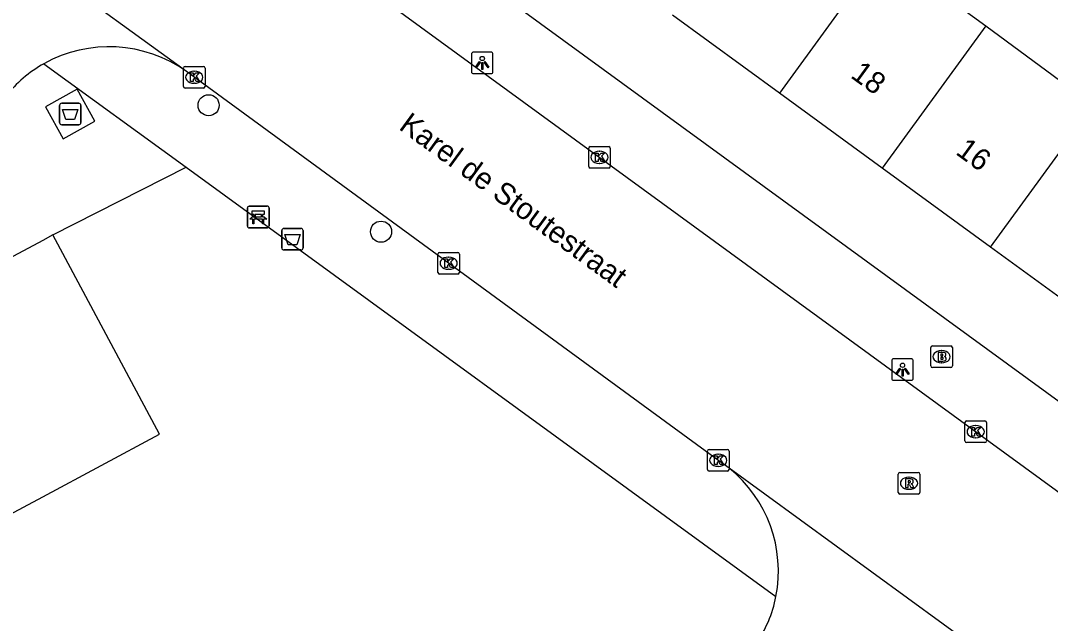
# Model space of a CAD drawing. Extents: x 159675 to 160530, y 382179 to 382901.
# Drawn here: x 159998.97 to 160046.7, y 382350.18 to 382378.09 of the extents above; entities that cross this region are included whole.
import ezdxf

# ---------------------------------------------------------------- set-up
doc = ezdxf.new("R2010")
doc.units = 0
for name, color, linetype in [('IMGEO_Afval_apart_plaats', 7, 'Continuous'), ('IMGEO_Afvalbak', 7, 'Continuous'), ('IMGEO_Bank', 7, 'Continuous'), ('IMGEO_Boom', 7, 'Continuous'), ('IMGEO_Brandkraan', 7, 'Continuous'), ('IMGEO_Kolk', 7, 'Continuous'), ('IMGEO_Lichtpunt', 7, 'Continuous'), ('IMGEO_Openbare_ruimte_label', 7, 'Continuous'), ('IMGEO_Pand', 7, 'Continuous'), ('IMGEO_Pand_nummerreeks', 7, 'Continuous'), ('IMGEO_Rijbaan_lokaal_gesloten', 7, 'Continuous'), ('IMGEO_Rijbaan_lokaal_open', 7, 'Continuous'), ('IMGEO_Rioolput', 7, 'Continuous'), ('IMGEO_Voetpad_gesloten', 7, 'Continuous'), ('IMGEO_Voetpad_open', 7, 'Continuous')]:
    doc.layers.add(name, color=color, linetype=linetype)

msp = doc.modelspace()

# ---------------------------------------------------------------- linework, layer by layer
at = {"layer": 'IMGEO_Afval_apart_plaats'}
for p, q in [((160000.777, 382373.368), (160000.777, 382374.168)), ((160000.777, 382374.168), (160000.777, 382373.368)), ((160000.877, 382374.268), (160001.667, 382374.268)), ((160001.667, 382374.268), (160000.877, 382374.268)), ((160001.767, 382374.168), (160001.767, 382373.368)), ((160001.767, 382373.368), (160001.767, 382374.168)), ((160001.667, 382373.268), (160000.877, 382373.268)), ((160000.877, 382373.268), (160001.667, 382373.268))]:
    msp.add_line(p, q, dxfattribs=at)
msp.add_lwpolyline([(160000.92, 382373.982), (160001.624, 382373.982), (160001.475, 382373.512), (160001.069, 382373.512), (160000.92, 382373.982)], dxfattribs=at)
for centre, start, end in [((160000.877, 382374.168), 90, 180), ((160000.877, 382374.168), 90, 180), ((160001.667, 382374.168), 0, 90), ((160001.667, 382374.168), 360, 90), ((160000.877, 382373.368), 180, 270), ((160000.877, 382373.368), 180, 270), ((160001.667, 382373.368), 270, 0), ((160001.667, 382373.368), 270, 0)]:
    msp.add_arc(centre, 0.1, start, end, dxfattribs=at)
at = {"layer": 'IMGEO_Afvalbak'}
for p, q in [((160011.077, 382367.57), (160011.077, 382368.37)), ((160011.077, 382368.37), (160011.077, 382367.57)), ((160011.177, 382368.47), (160011.967, 382368.47)), ((160011.967, 382368.47), (160011.177, 382368.47)), ((160012.067, 382368.37), (160012.067, 382367.57)), ((160012.067, 382367.57), (160012.067, 382368.37)), ((160011.967, 382367.47), (160011.177, 382367.47)), ((160011.177, 382367.47), (160011.967, 382367.47))]:
    msp.add_line(p, q, dxfattribs=at)
msp.add_lwpolyline([(160011.22, 382368.184), (160011.924, 382368.184), (160011.775, 382367.714), (160011.369, 382367.714), (160011.22, 382368.184)], dxfattribs=at)
for centre, start, end in [((160011.177, 382368.37), 90, 180), ((160011.177, 382368.37), 90, 180), ((160011.967, 382368.37), 0, 90), ((160011.967, 382368.37), 360, 90), ((160011.177, 382367.57), 180, 270), ((160011.177, 382367.57), 180, 270), ((160011.967, 382367.57), 270, 0), ((160011.967, 382367.57), 270, 0)]:
    msp.add_arc(centre, 0.1, start, end, dxfattribs=at)
at = {"layer": 'IMGEO_Bank'}
for p, q in [((160009.486, 382368.574), (160009.486, 382369.415)), ((160009.486, 382369.415), (160009.486, 382368.574)), ((160009.561, 382369.499), (160010.402, 382369.499)), ((160010.402, 382369.499), (160009.561, 382369.499)), ((160010.486, 382369.424), (160010.486, 382368.583)), ((160010.486, 382368.583), (160010.486, 382369.424)), ((160010.183, 382368.897), (160009.79, 382368.897)), ((160009.795, 382369.005), (160009.795, 382369.111)), ((160009.839, 382369.111), (160009.839, 382369.005)), ((160010.127, 382369.117), (160009.845, 382369.117)), ((160009.845, 382368.999), (160010.127, 382368.999)), ((160010.133, 382369.005), (160010.133, 382369.111)), ((160010.177, 382369.111), (160010.177, 382369.005)), ((160010.411, 382368.499), (160009.57, 382368.499)), ((160009.57, 382368.499), (160010.411, 382368.499))]:
    msp.add_line(p, q, dxfattribs=at)
for points in [[(160009.789, 382369.117), (160009.703, 382369.117), (160009.703, 382369.278), (160010.266, 382369.278), (160010.266, 382369.117), (160010.183, 382369.117)], [(160009.733, 382368.897), (160009.591, 382368.897), (160009.703, 382368.999), (160009.789, 382368.999)], [(160009.783, 382368.89), (160009.783, 382368.683), (160009.74, 382368.683), (160009.74, 382368.89)], [(160010.183, 382368.999), (160010.266, 382368.999), (160010.378, 382368.897), (160010.239, 382368.897)], [(160010.233, 382368.89), (160010.233, 382368.683), (160010.189, 382368.683), (160010.189, 382368.89)]]:
    msp.add_lwpolyline(points, dxfattribs=at)
for centre, radius, start, end in [((160009.564, 382369.421), 0.0779, 92.4484, 184.2845), ((160009.564, 382369.421), 0.0779, 92.4484, 184.2845), ((160010.408, 382369.421), 0.0779, 2.4484, 94.2845), ((160010.408, 382369.421), 0.0779, 2.4484, 94.2845), ((160009.733, 382368.89), 0.00671, 2.8957, 87.1043), ((160009.79, 382368.89), 0.00671, 92.8957, 177.1043), ((160009.788, 382369.11), 0.00671, 2.8957, 87.1043), ((160009.788, 382369.006), 0.00671, 272.8957, 357.1043), ((160009.845, 382369.11), 0.00671, 92.8957, 177.1043), ((160009.845, 382369.006), 0.00671, 182.8957, 267.1043), ((160010.127, 382369.11), 0.00671, 2.8957, 87.1043), ((160010.127, 382369.006), 0.00671, 272.8957, 357.1043), ((160010.184, 382369.11), 0.00671, 92.8957, 177.1043), ((160010.184, 382369.006), 0.00671, 182.8957, 267.1043), ((160010.182, 382368.89), 0.00671, 2.8957, 87.1043), ((160010.239, 382368.89), 0.00671, 92.8957, 177.1043), ((160009.564, 382368.577), 0.0779, 182.4484, 274.2845), ((160009.564, 382368.577), 0.0779, 182.4484, 274.2845), ((160010.408, 382368.577), 0.0779, 272.4484, 4.2845), ((160010.408, 382368.577), 0.0779, 272.4484, 4.2845)]:
    msp.add_arc(centre, radius, start, end, dxfattribs=at)
at = {"layer": 'IMGEO_Boom'}
for centre in [(160007.684, 382374.173), (160015.678, 382368.317)]:
    msp.add_circle(centre, 0.489, dxfattribs=at)
at = {"layer": 'IMGEO_Brandkraan'}
for p, q in [((160041.155, 382362.103), (160041.155, 382362.955)), ((160041.23, 382363.029), (160042.082, 382363.029)), ((160041.643, 382362.809), (160041.668, 382362.809)), ((160042.156, 382362.955), (160042.156, 382362.103)), ((160041.666, 382362.249), (160041.641, 382362.249)), ((160042.082, 382362.029), (160041.23, 382362.029))]:
    msp.add_line(p, q, dxfattribs=at)
for points in [[(160041.155, 382362.103), (160041.155, 382362.955)], [(160041.23, 382363.029), (160042.082, 382363.029)], [(160041.503, 382362.729), (160041.503, 382362.329), (160041.716, 382362.329)], [(160041.734, 382362.729), (160041.503, 382362.729)], [(160041.682, 382362.648), (160041.628, 382362.648), (160041.628, 382362.572)], [(160041.628, 382362.572), (160041.681, 382362.572)], [(160042.156, 382362.955), (160042.156, 382362.103)], [(160041.69, 382362.496), (160041.628, 382362.496), (160041.628, 382362.415)], [(160041.628, 382362.415), (160041.69, 382362.415)], [(160042.082, 382362.029), (160041.23, 382362.029)]]:
    msp.add_lwpolyline(points, dxfattribs=at)
for centre, radius, start, end in [((160041.232, 382362.953), 0.0765, 91.552, 178.448), ((160041.232, 382362.953), 0.0765, 91.552, 178.448), ((160041.683, 382362.61), 0.0379, 267.8285, 90.9355), ((160041.738, 382362.584), 0.145, 59.4692, 91.5367), ((160041.763, 382362.631), 0.0922, 285.5137, 58.1501), ((160042.08, 382362.953), 0.0765, 1.552, 88.448), ((160042.08, 382362.953), 0.0765, 1.552, 88.448), ((160041.232, 382362.105), 0.0765, 181.552, 268.448), ((160041.232, 382362.105), 0.0765, 181.552, 268.448), ((160041.691, 382362.455), 0.0404, 269.8759, 90.5077), ((160041.722, 382362.58), 0.251, 268.6676, 293.5347), ((160041.768, 382362.439), 0.105, 301.3115, 78.989), ((160042.08, 382362.105), 0.0765, 271.552, 358.448), ((160042.08, 382362.105), 0.0765, 271.552, 358.448)]:
    msp.add_arc(centre, radius, start, end, dxfattribs=at)
for centre, major_axis, ratio, start_param, end_param in [((160041.642, 382362.529), (-0.387, 0.002), 0.722429, 4.712389, 7.853982), ((160041.667, 382362.529), (-0.39, 0.002), 0.717154, 1.570796, 4.712389)]:
    msp.add_ellipse(centre, major_axis=major_axis, ratio=ratio, start_param=start_param, end_param=end_param, dxfattribs=at)
at = {"layer": 'IMGEO_Kolk'}
for p, q in [((160006.593, 382375.967), (160007.445, 382375.967)), ((160006.518, 382375.041), (160006.518, 382375.893)), ((160007.006, 382375.747), (160007.031, 382375.747)), ((160007.519, 382375.893), (160007.519, 382375.041)), ((160007.445, 382374.967), (160006.593, 382374.967)), ((160007.029, 382375.187), (160007.004, 382375.187)), ((160025.3, 382371.334), (160025.3, 382372.186)), ((160025.375, 382372.26), (160026.227, 382372.26)), ((160026.301, 382372.186), (160026.301, 382371.334)), ((160025.788, 382372.04), (160025.813, 382372.04)), ((160026.227, 382371.26), (160025.375, 382371.26)), ((160025.811, 382371.48), (160025.786, 382371.48)), ((160018.385, 382367.356), (160019.237, 382367.356)), ((160018.31, 382366.43), (160018.31, 382367.282)), ((160018.798, 382367.136), (160018.823, 382367.136)), ((160019.311, 382367.282), (160019.311, 382366.43)), ((160018.821, 382366.576), (160018.796, 382366.576)), ((160019.237, 382366.356), (160018.385, 382366.356)), ((160042.737, 382358.63), (160042.737, 382359.482)), ((160042.812, 382359.556), (160043.664, 382359.556)), ((160043.225, 382359.336), (160043.25, 382359.336)), ((160043.738, 382359.482), (160043.738, 382358.63)), ((160043.248, 382358.776), (160043.223, 382358.776)), ((160043.664, 382358.556), (160042.812, 382358.556)), ((160030.804, 382357.306), (160030.804, 382358.158)), ((160030.879, 382358.232), (160031.731, 382358.232)), ((160031.292, 382358.012), (160031.317, 382358.012)), ((160031.805, 382358.158), (160031.805, 382357.306)), ((160031.315, 382357.452), (160031.29, 382357.452)), ((160031.731, 382357.232), (160030.879, 382357.232))]:
    msp.add_line(p, q, dxfattribs=at)
for points in [[(160006.593, 382375.967), (160007.445, 382375.967)], [(160006.518, 382375.041), (160006.518, 382375.893)], [(160006.839, 382375.667), (160006.962, 382375.667), (160006.962, 382375.516), (160007.092, 382375.667), (160007.256, 382375.667), (160007.11, 382375.516), (160007.263, 382375.267), (160007.111, 382375.267), (160007.026, 382375.431), (160006.962, 382375.364), (160006.962, 382375.267), (160006.839, 382375.267), (160006.839, 382375.667)], [(160007.519, 382375.893), (160007.519, 382375.041)], [(160007.445, 382374.967), (160006.593, 382374.967)], [(160025.3, 382371.334), (160025.3, 382372.186)], [(160025.375, 382372.26), (160026.227, 382372.26)], [(160026.301, 382372.186), (160026.301, 382371.334)], [(160025.621, 382371.96), (160025.744, 382371.96), (160025.744, 382371.809), (160025.874, 382371.96), (160026.038, 382371.96), (160025.892, 382371.809), (160026.045, 382371.56), (160025.893, 382371.56), (160025.808, 382371.724), (160025.744, 382371.657), (160025.744, 382371.56), (160025.621, 382371.56), (160025.621, 382371.96)], [(160026.227, 382371.26), (160025.375, 382371.26)], [(160018.385, 382367.356), (160019.237, 382367.356)], [(160018.31, 382366.43), (160018.31, 382367.282)], [(160018.631, 382367.056), (160018.754, 382367.056), (160018.754, 382366.905), (160018.884, 382367.056), (160019.048, 382367.056), (160018.902, 382366.905), (160019.055, 382366.656), (160018.903, 382366.656), (160018.818, 382366.82), (160018.754, 382366.753), (160018.754, 382366.656), (160018.631, 382366.656), (160018.631, 382367.056)], [(160019.311, 382367.282), (160019.311, 382366.43)], [(160019.237, 382366.356), (160018.385, 382366.356)], [(160042.737, 382358.63), (160042.737, 382359.482)], [(160042.812, 382359.556), (160043.664, 382359.556)], [(160043.058, 382359.256), (160043.181, 382359.256), (160043.181, 382359.105), (160043.311, 382359.256), (160043.475, 382359.256), (160043.329, 382359.105), (160043.482, 382358.856), (160043.33, 382358.856), (160043.245, 382359.02), (160043.181, 382358.953), (160043.181, 382358.856), (160043.058, 382358.856), (160043.058, 382359.256)], [(160043.738, 382359.482), (160043.738, 382358.63)], [(160043.664, 382358.556), (160042.812, 382358.556)], [(160030.804, 382357.306), (160030.804, 382358.158)], [(160030.879, 382358.232), (160031.731, 382358.232)], [(160031.125, 382357.932), (160031.248, 382357.932), (160031.248, 382357.781), (160031.378, 382357.932), (160031.542, 382357.932), (160031.396, 382357.781), (160031.549, 382357.532), (160031.397, 382357.532), (160031.312, 382357.696), (160031.248, 382357.629), (160031.248, 382357.532), (160031.125, 382357.532), (160031.125, 382357.932)], [(160031.805, 382358.158), (160031.805, 382357.306)], [(160031.731, 382357.232), (160030.879, 382357.232)]]:
    msp.add_lwpolyline(points, dxfattribs=at)
for centre, start, end in [((160006.595, 382375.891), 91.552, 178.448), ((160006.595, 382375.891), 91.552, 178.448), ((160007.443, 382375.891), 1.552, 88.448), ((160007.443, 382375.891), 1.552, 88.448), ((160006.595, 382375.043), 181.552, 268.448), ((160006.595, 382375.043), 181.552, 268.448), ((160007.443, 382375.043), 271.552, 358.448), ((160007.443, 382375.043), 271.552, 358.448), ((160025.377, 382372.184), 91.552, 178.448), ((160025.377, 382372.184), 91.552, 178.448), ((160026.225, 382372.184), 1.552, 88.448), ((160026.225, 382372.184), 1.552, 88.448), ((160025.377, 382371.336), 181.552, 268.448), ((160025.377, 382371.336), 181.552, 268.448), ((160026.225, 382371.336), 271.552, 358.448), ((160026.225, 382371.336), 271.552, 358.448), ((160018.387, 382367.28), 91.552, 178.448), ((160018.387, 382367.28), 91.552, 178.448), ((160019.235, 382367.28), 1.552, 88.448), ((160019.235, 382367.28), 1.552, 88.448), ((160018.387, 382366.432), 181.552, 268.448), ((160018.387, 382366.432), 181.552, 268.448), ((160019.235, 382366.432), 271.552, 358.448), ((160019.235, 382366.432), 271.552, 358.448), ((160042.814, 382359.48), 91.552, 178.448), ((160042.814, 382359.48), 91.552, 178.448), ((160043.662, 382359.48), 1.552, 88.448), ((160043.662, 382359.48), 1.552, 88.448), ((160042.814, 382358.632), 181.552, 268.448), ((160042.814, 382358.632), 181.552, 268.448), ((160043.662, 382358.632), 271.552, 358.448), ((160043.662, 382358.632), 271.552, 358.448), ((160030.881, 382358.156), 91.552, 178.448), ((160030.881, 382358.156), 91.552, 178.448), ((160031.729, 382358.156), 1.552, 88.448), ((160031.729, 382358.156), 1.552, 88.448), ((160030.881, 382357.308), 181.552, 268.448), ((160030.881, 382357.308), 181.552, 268.448), ((160031.729, 382357.308), 271.552, 358.448), ((160031.729, 382357.308), 271.552, 358.448)]:
    msp.add_arc(centre, 0.0765, start, end, dxfattribs=at)
for centre, major_axis, ratio, start_param, end_param in [((160007.005, 382375.467), (-0.387, 0.002), 0.722429, 4.712389, 7.853982), ((160007.03, 382375.467), (-0.39, 0.002), 0.717154, 1.570796, 4.712389), ((160025.787, 382371.76), (-0.387, 0.002), 0.722429, 4.712389, 7.853982), ((160025.812, 382371.76), (-0.39, 0.002), 0.717154, 1.570796, 4.712389), ((160018.797, 382366.856), (-0.387, 0.002), 0.722429, 4.712389, 7.853982), ((160018.822, 382366.856), (-0.39, 0.002), 0.717154, 1.570796, 4.712389), ((160043.224, 382359.056), (-0.387, 0.002), 0.722429, 4.712389, 7.853982), ((160043.249, 382359.056), (-0.39, 0.002), 0.717154, 1.570796, 4.712389), ((160031.291, 382357.732), (-0.387, 0.002), 0.722429, 4.712389, 7.853982), ((160031.316, 382357.732), (-0.39, 0.002), 0.717154, 1.570796, 4.712389)]:
    msp.add_ellipse(centre, major_axis=major_axis, ratio=ratio, start_param=start_param, end_param=end_param, dxfattribs=at)
at = {"layer": 'IMGEO_Lichtpunt'}
for p, q in [((160019.868, 382376.538), (160019.868, 382375.731)), ((160019.868, 382376.538), (160019.868, 382375.731)), ((160020.77, 382376.633), (160019.962, 382376.633)), ((160020.77, 382376.633), (160019.962, 382376.633)), ((160020.864, 382375.731), (160020.864, 382376.538)), ((160020.864, 382375.731), (160020.864, 382376.538)), ((160019.962, 382375.637), (160020.77, 382375.637)), ((160019.962, 382375.637), (160020.77, 382375.637)), ((160039.347, 382362.337), (160039.347, 382361.53)), ((160039.347, 382362.337), (160039.347, 382361.53)), ((160040.249, 382362.432), (160039.441, 382362.432)), ((160040.249, 382362.432), (160039.441, 382362.432)), ((160040.343, 382361.53), (160040.343, 382362.337)), ((160040.343, 382361.53), (160040.343, 382362.337)), ((160039.441, 382361.436), (160040.249, 382361.436)), ((160039.441, 382361.436), (160040.249, 382361.436))]:
    msp.add_line(p, q, dxfattribs=at)
for points in [[(160020.242, 382376.202), (160020.281, 382376.174), (160020.093, 382375.912), (160020.055, 382375.939), (160020.242, 382376.202)], [(160020.344, 382376.154), (160020.391, 382376.154), (160020.391, 382375.832), (160020.344, 382375.832), (160020.344, 382376.154)], [(160020.454, 382376.174), (160020.492, 382376.201), (160020.679, 382375.939), (160020.64, 382375.911), (160020.454, 382376.174)], [(160039.721, 382362.001), (160039.76, 382361.973), (160039.572, 382361.711), (160039.534, 382361.738), (160039.721, 382362.001)], [(160039.823, 382361.953), (160039.87, 382361.953), (160039.87, 382361.631), (160039.823, 382361.631), (160039.823, 382361.953)], [(160039.933, 382361.973), (160039.971, 382362), (160040.158, 382361.738), (160040.119, 382361.71), (160039.933, 382361.973)]]:
    msp.add_lwpolyline(points, dxfattribs=at)
for centre in [(160020.367, 382376.336), (160039.846, 382362.135)]:
    msp.add_circle(centre, 0.0994, dxfattribs=at)
for centre, start, end in [((160019.962, 382376.538), 90, 180), ((160019.962, 382376.538), 90, 180), ((160020.77, 382376.538), 0, 90), ((160020.77, 382376.538), 0, 90), ((160019.962, 382375.731), 180, 270), ((160019.962, 382375.731), 180, 270), ((160020.77, 382375.731), 270, 0), ((160020.77, 382375.731), 270, 360), ((160039.441, 382362.337), 90, 180), ((160039.441, 382362.337), 90, 180), ((160040.249, 382362.337), 0, 90), ((160040.249, 382362.337), 0, 90), ((160039.441, 382361.53), 180, 270), ((160039.441, 382361.53), 180, 270), ((160040.249, 382361.53), 270, 0), ((160040.249, 382361.53), 270, 360)]:
    msp.add_arc(centre, 0.0946, start, end, dxfattribs=at)
at = {"layer": 'IMGEO_Pand'}
for points in [[(160038.941, 382381.325), (160034.141, 382374.737)], [(160038.941, 382381.325), (160043.71, 382377.851)], [(160034.141, 382374.737), (160029.188, 382378.345)], [(160043.71, 382377.851), (160038.909, 382371.263)], [(160043.71, 382377.851), (160048.708, 382374.167)], [(160038.909, 382371.263), (160034.141, 382374.737)], [(160043.927, 382367.607), (160048.708, 382374.167)], [(160043.927, 382367.607), (160038.909, 382371.263)], [(160000.468, 382368.176), (160000, 382367.916), (159984.966, 382359.895)], [(159989.896, 382350.653), (160000, 382356.044), (160005.403, 382358.937), (160000.468, 382368.176)], [(160048.682, 382364.143), (160043.927, 382367.607)]]:
    msp.add_lwpolyline(points, dxfattribs=at)
at = {"layer": 'IMGEO_Rijbaan_lokaal_gesloten'}
for points in [[(160078.11, 382333.649), (160000, 382390.554), (159999.175, 382391.156)], [(160006.662, 382375.729), (160000, 382380.567), (159992.936, 382385.697)], [(160031.812, 382357.364), (160031.337, 382357.71), (160006.662, 382375.729)], [(160045.029, 382347.737), (160031.812, 382357.364)]]:
    msp.add_lwpolyline(points, dxfattribs=at)
at = {"layer": 'IMGEO_Rijbaan_lokaal_open'}
for centre, radius, start, end in [((160003.062, 382370.677), 6.203, 54.5249, 119.1097), ((160003.274, 382370.503), 6.46, 120.0051, 140.6939), ((160027.972, 382352.595), 6.123, 348.9859, 51.1569), ((160028.662, 382352.413), 5.41, 323.7202, 349.4834)]:
    msp.add_arc(centre, radius, start, end, dxfattribs=at)
at = {"layer": 'IMGEO_Rioolput'}
for p, q in [((160039.647, 382356.242), (160039.647, 382357.094)), ((160039.722, 382357.168), (160040.574, 382357.168)), ((160040.135, 382356.948), (160040.16, 382356.948)), ((160040.648, 382357.094), (160040.648, 382356.242)), ((160040.158, 382356.388), (160040.133, 382356.388)), ((160040.574, 382356.168), (160039.722, 382356.168))]:
    msp.add_line(p, q, dxfattribs=at)
for points in [[(160039.647, 382356.242), (160039.647, 382357.094)], [(160039.722, 382357.168), (160040.574, 382357.168)], [(160040.236, 382356.866), (160039.984, 382356.868), (160039.984, 382356.468)], [(160040.648, 382357.094), (160040.648, 382356.242)], [(160039.984, 382356.468), (160040.108, 382356.468), (160040.108, 382356.63), (160040.119, 382356.63)], [(160040.162, 382356.787), (160040.108, 382356.787), (160040.108, 382356.706)], [(160040.108, 382356.706), (160040.16, 382356.706)], [(160040.166, 382356.601), (160040.237, 382356.468), (160040.377, 382356.468), (160040.312, 382356.594)], [(160040.574, 382356.168), (160039.722, 382356.168)]]:
    msp.add_lwpolyline(points, dxfattribs=at)
for centre, radius, start, end in [((160039.724, 382357.092), 0.0765, 91.552, 178.448), ((160039.724, 382357.092), 0.0765, 91.552, 178.448), ((160040.235, 382356.756), 0.109, 350.3612, 89.416), ((160040.572, 382357.092), 0.0765, 1.552, 88.448), ((160040.572, 382357.092), 0.0765, 1.552, 88.448), ((160040.118, 382356.577), 0.0533, 26.0293, 88.6989), ((160040.144, 382356.895), 0.19, 274.7715, 282.9687), ((160040.168, 382356.691), 0.0964, 77.0061, 93.1865), ((160040.182, 382356.748), 0.0378, 276.6634, 79.6772), ((160040.233, 382356.756), 0.112, 277.5842, 350.9817), ((160040.217, 382356.541), 0.108, 29.5134, 73.7905), ((160039.724, 382356.244), 0.0765, 181.552, 268.448), ((160039.724, 382356.244), 0.0765, 181.552, 268.448), ((160040.572, 382356.244), 0.0765, 271.552, 358.448), ((160040.572, 382356.244), 0.0765, 271.552, 358.448)]:
    msp.add_arc(centre, radius, start, end, dxfattribs=at)
for centre, major_axis, ratio, start_param, end_param in [((160040.134, 382356.668), (-0.387, 0.002), 0.722429, 4.712389, 7.853982), ((160040.159, 382356.668), (-0.39, 0.002), 0.717154, 1.570796, 4.712389)]:
    msp.add_ellipse(centre, major_axis=major_axis, ratio=ratio, start_param=start_param, end_param=end_param, dxfattribs=at)
at = {"layer": 'IMGEO_Voetpad_gesloten'}
msp.add_lwpolyline([(160001.596, 382374.914), (160000.131, 382374.105), (160000.949, 382372.623), (160002.414, 382373.432), (160001.596, 382374.914)], dxfattribs=at)
at = {"layer": 'IMGEO_Voetpad_open'}
for points in [[(160002.502, 382392.948), (160051.264, 382357.423)], [(160000.044, 382376.097), (160006.646, 382371.299)], [(160000.468, 382368.176), (160006.646, 382371.299)], [(160006.646, 382371.299), (160033.982, 382351.425)]]:
    msp.add_lwpolyline(points, dxfattribs=at)

# ---------------------------------------------------------------- texts
at = {"layer": 'IMGEO_Openbare_ruimte_label'}
msp.add_text('Karel de Stoutestraat', height=1, rotation=323.8632, dxfattribs=at).set_placement((160016.455, 382373.092))
at = {"layer": 'IMGEO_Pand_nummerreeks'}
for s, p in [('18', (160037.392, 382375.486)), ('16', (160042.265, 382371.935))]:
    msp.add_text(s, height=1, rotation=323.9266, dxfattribs=at).set_placement(p)

doc.saveas('drawing.dxf')
